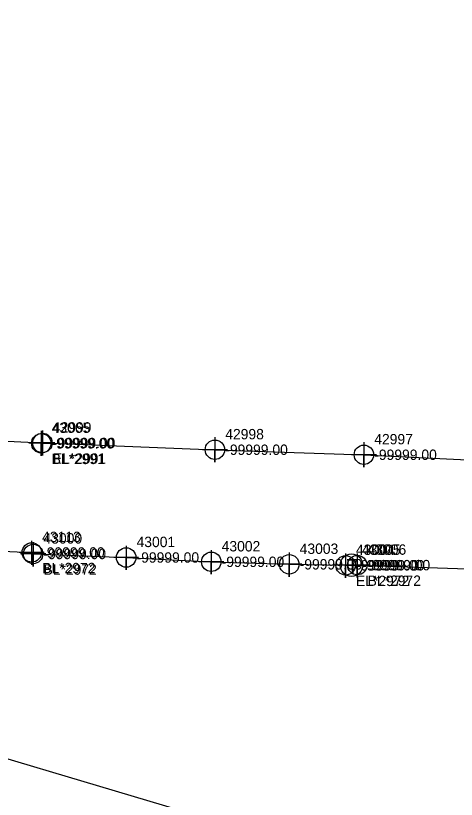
# Model space of a CAD drawing. Extents: x 2083698 to 2094313, y 743246 to 752873.
# Drawn here: x 2093138.5 to 2093244.6, y 746831.1 to 747019.8 of the extents above; entities that cross this region are included whole.
import ezdxf

# ---------------------------------------------------------------- set-up
doc = ezdxf.new("R2010")
doc.units = 0
for name, color, linetype in [('COGO Default Point Number', 7, 'Continuous'), ('Exist Property Line', 7, 'Continuous'), ('Exist Right of Way Line', 7, 'Continuous'), ('Exist Right of Way Line Leader', 7, 'Continuous'), ('Exist Right of Way Line Text', 7, 'Continuous'), ('Exist Right of Way Width CELL', 7, 'Continuous'), ('Exist Structure Minor Pipes RCP 12 Inch', 7, 'Continuous'), ('Exist Utilities Power UG Cable SUE LOS C', 7, 'Continuous'), ('Exist Utilities Sanitary Sewer UG Line', 7, 'Continuous'), ('Exist Utilities Telephone UG Conduit SUE LOS B', 7, 'Continuous'), ('Exist Utilities Water UG Line SUE LOS B', 7, 'Continuous'), ('Scratch_Level_2', 7, 'Continuous'), ('Scratch_Level_3', 7, 'Continuous')]:
    doc.layers.add(name, color=color, linetype=linetype)

msp = doc.modelspace()

# ---------------------------------------------------------------- linework, layer by layer
at = {"layer": 'COGO Default Point Number'}
for points in [[(2093144.67, 746919.85), (2093144.67, 746913.85), (2093144.67, 746916.85), (2093147.67, 746916.85), (2093141.67, 746916.85)], [(2093144.95, 746919.94), (2093144.95, 746913.94), (2093144.95, 746916.94), (2093147.95, 746916.94), (2093141.95, 746916.94)], [(2093186.47, 746918.31), (2093186.47, 746912.31), (2093186.47, 746915.31), (2093189.47, 746915.31), (2093183.47, 746915.31)], [(2093222.34, 746917.1), (2093222.34, 746911.1), (2093222.34, 746914.1), (2093225.34, 746914.1), (2093219.34, 746914.1)]]:
    msp.add_lwpolyline(points, dxfattribs=at)
for centre in [(2093144.67, 746916.85), (2093144.95, 746916.94), (2093186.47, 746915.31), (2093222.34, 746914.1)]:
    msp.add_circle(centre, 2.34, dxfattribs=at)
at = {"layer": 'Exist Right of Way Line Text'}
for points in [[(2093142.35, 746893.38), (2093142.38, 746887.57), (2093142.37, 746890.57), (2093145.38, 746890.57), (2093139.38, 746890.57)], [(2093142.68, 746893.03), (2093142.71, 746887.21), (2093142.69, 746890.21), (2093145.71, 746890.21), (2093139.71, 746890.21)], [(2093165.08, 746892.17), (2093165.11, 746886.36), (2093165.1, 746889.36), (2093168.11, 746889.36), (2093162.11, 746889.36)], [(2093185.57, 746891.13), (2093185.6, 746885.32), (2093185.58, 746888.32), (2093188.6, 746888.32), (2093182.6, 746888.32)], [(2093204.35, 746890.53), (2093204.38, 746884.72), (2093204.36, 746887.72), (2093207.38, 746887.72), (2093201.38, 746887.72)], [(2093217.91, 746890.3), (2093217.94, 746884.48), (2093217.92, 746887.48), (2093220.94, 746887.48), (2093214.94, 746887.48)], [(2093220.71, 746890.33), (2093220.74, 746884.52), (2093220.73, 746887.52), (2093223.74, 746887.52), (2093217.74, 746887.52)]]:
    msp.add_lwpolyline(points, dxfattribs=at)
for centre in [(2093142.38, 746890.57), (2093142.71, 746890.21), (2093165.11, 746889.36), (2093185.6, 746888.32), (2093204.38, 746887.72), (2093217.94, 746887.48), (2093220.74, 746887.52)]:
    msp.add_circle(centre, 2.34, dxfattribs=at)
at = {"layer": 'Exist Utilities Power UG Cable SUE LOS C'}
msp.add_lwpolyline([(2091387.72, 747754.05), (2091459.29, 747488.14), (2091734.16, 747369.44), (2092190.29, 747172.26), (2092598.52, 747024.9), (2092972.51, 746889.78), (2093316.78, 746787.16), (2093711.24, 746532.37)], dxfattribs=at)
at = {"layer": 'Exist Utilities Telephone UG Conduit SUE LOS B'}
for points in [[(2092918.55, 746900.6), (2092938.65, 746899.11), (2092967.03, 746897.79), (2092994.21, 746896.53), (2093036.14, 746894.5), (2093057.99, 746893.19), (2093089.42, 746892.72), (2093117.56, 746891.69), (2093142.38, 746890.57)], [(2093142.71, 746890.21), (2093165.11, 746889.36), (2093185.6, 746888.32), (2093204.38, 746887.72), (2093217.94, 746887.48)], [(2093220.74, 746887.52), (2093249.72, 746886.52), (2093276.76, 746886.41), (2093299.29, 746884.96), (2093321.38, 746882.93), (2093341.35, 746881.8), (2093354.66, 746881.3), (2093444.11, 746880.76)]]:
    msp.add_lwpolyline(points, dxfattribs=at)
at = {"layer": 'Exist Utilities Water UG Line SUE LOS B'}
for points in [[(2093144.67, 746916.85), (2093120.21, 746918.09), (2093092.87, 746919.21)], [(2093144.95, 746916.94), (2093186.47, 746915.31), (2093222.34, 746914.1), (2093250.54, 746912.7), (2093279.52, 746911), (2093300.2, 746910.52), (2093315.86, 746909.13), (2093335.3, 746907.43), (2093352.6, 746909.21), (2093358.87, 746910.97)]]:
    msp.add_lwpolyline(points, dxfattribs=at)
msp.add_circle((2093219.38, 746887.49), 2.72, dxfattribs=at)

# ---------------------------------------------------------------- texts
at = {"layer": 'Exist Property Line'}
for p in [(2093147.17, 746915.6), (2093147.45, 746915.69), (2093188.97, 746914.06), (2093224.84, 746912.85)]:
    msp.add_text('-99999.00', height=2.5, dxfattribs=at).set_placement(p)
at = {"layer": 'Exist Right of Way Line'}
for s, p in [('43065', (2093147.17, 746919.35)), ('42999', (2093147.45, 746919.44)), ('42998', (2093188.97, 746917.81)), ('42997', (2093224.84, 746916.6))]:
    msp.add_text(s, height=2.5, dxfattribs=at).set_placement(p)
at = {"layer": 'Exist Right of Way Line Leader'}
for s, p in [('43113', (2093144.88, 746893.07)), ('43000', (2093145.21, 746892.71)), ('43001', (2093167.61, 746891.86)), ('43002', (2093188.1, 746890.82)), ('43003', (2093206.88, 746890.22)), ('43004', (2093220.44, 746889.98)), ('43006', (2093223.24, 746890.02))]:
    msp.add_text(s, height=2.5, dxfattribs=at).set_placement(p)
at = {"layer": 'Exist Right of Way Width CELL'}
for s, p in [('BL*2991', (2093147.17, 746911.85)), ('EL*2991', (2093147.45, 746911.94))]:
    msp.add_text(s, height=2.5, dxfattribs=at).set_placement(p)
at = {"layer": 'Exist Structure Minor Pipes RCP 12 Inch'}
msp.add_text('43005', height=2.5, dxfattribs=at).set_placement((2093221.87, 746889.99))
at = {"layer": 'Exist Utilities Sanitary Sewer UG Line'}
msp.add_text('-99999.00', height=2.5, dxfattribs=at).set_placement((2093221.87, 746886.24))
at = {"layer": 'Exist Utilities Water UG Line SUE LOS B'}
msp.add_text('T', height=3.5, dxfattribs=at).set_placement((2093218.2, 746885.48))
at = {"layer": 'Scratch_Level_2'}
for p in [(2093144.88, 746889.32), (2093145.21, 746888.96), (2093167.61, 746888.11), (2093188.1, 746887.07), (2093206.88, 746886.47), (2093220.44, 746886.23), (2093223.24, 746886.27)]:
    msp.add_text('-99999.00', height=2.5, dxfattribs=at).set_placement(p)
at = {"layer": 'Scratch_Level_3'}
for s, p in [('BL*2972', (2093144.88, 746885.57)), ('BL*2972', (2093145.21, 746885.21)), ('EL*2972', (2093220.44, 746882.48)), ('BL*2972', (2093223.24, 746882.52))]:
    msp.add_text(s, height=2.5, dxfattribs=at).set_placement(p)

doc.saveas('drawing.dxf')
